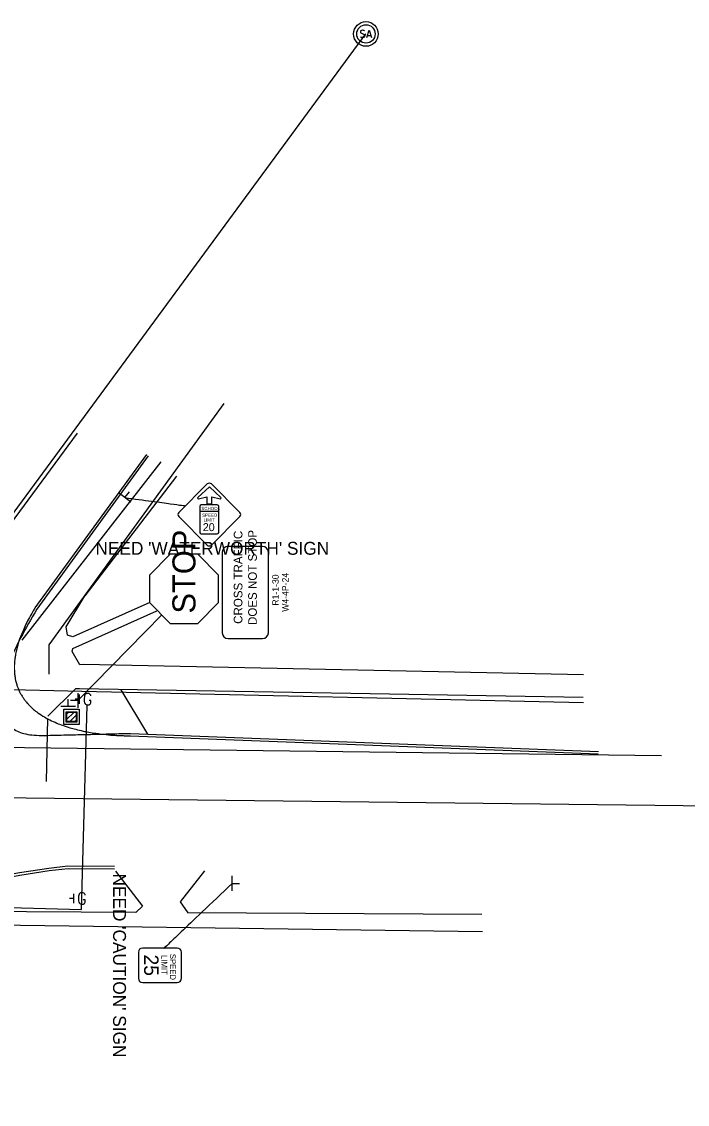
# Model space of a CAD drawing. Extents: x 108269 to 109415, y 548506 to 548874.
# Drawn here: x 109069.3 to 109213.8, y 548639.3 to 548874.1 of the extents above; entities that cross this region are included whole.
import ezdxf

# ---------------------------------------------------------------- set-up
doc = ezdxf.new("R2010")
doc.units = 0
for name, color, linetype in [('Default', 7, 'Continuous'), ('SC_Scratch1', 7, 'Continuous'), ('SH_Data', 7, 'Continuous'), ('SH_Text', 7, 'Continuous'), ('SN_P_Post', 7, 'Continuous'), ('SN_P_Signs', 7, 'Continuous'), ('SN_P_Text', 7, 'Continuous'), ('SN_X_Post', 7, 'Continuous'), ('SN_X_Public', 7, 'Continuous')]:
    doc.layers.add(name, color=color, linetype=linetype)

msp = doc.modelspace()

# ---------------------------------------------------------------- linework, layer by layer
at = {"layer": 'Default'}
for p, q in [((109144.06, 548873.47), (109144.06, 548873.47)), ((109022.45, 548706.36), (109144.06, 548871.47)), ((109144.06, 548871.47), (109144.06, 548871.47)), ((109144.06, 548871.47), (109144.06, 548871.47)), ((109144.06, 548871.47), (109144.06, 548871.47)), ((109144.06, 548869.47), (109144.06, 548869.47)), ((109048.43, 548740.21), (109081.46, 548784.86)), ((109096.41, 548780.23), (109072.22, 548746.98)), ((109096.81, 548779.93), (109072.63, 548746.68)), ((109099.53, 548778.68), (109069.36, 548739.94)), ((109102.97, 548775.55), (109083.03, 548749.59)), ((109078.99, 548742.87), (109083.03, 548749.59)), ((109080.41, 548738.19), (109098.7, 548746.34)), ((109097.19, 548748.16), (109080.47, 548740.7)), ((109079.25, 548741.06), (109078.99, 548742.87)), ((109080.47, 548740.7), (109079.25, 548741.06)), ((109080.3, 548737.51), (109080.41, 548738.19)), ((109081.95, 548734.64), (109080.3, 548737.51)), ((109082.76, 548734.69), (109081.95, 548734.64)), ((109191.28, 548732.44), (109082.76, 548734.69)), ((108915.58, 548732.79), (109082.36, 548728.91)), ((109081.01, 548729.39), (109074.99, 548723.51)), ((109081.88, 548729.38), (109081.01, 548729.39)), ((109191.25, 548727.49), (109081.88, 548729.38)), ((109081.91, 548726.16), (109081.91, 548728.16)), ((109082.36, 548728.91), (109191.28, 548726.42)), ((109090.84, 548729.22), (109096.63, 548719.59)), ((109080.16, 548724.97), (109080.16, 548724.97)), ((109081.91, 548727.16), (109080.95, 548727.16)), ((109082.29, 548681.55), (109083.58, 548725.84)), ((109074.92, 548722.94), (109074.65, 548709.3)), ((109079.01, 548722.69), (109080.77, 548724.45)), ((109079.01, 548723.82), (109079.64, 548724.45)), ((109079.16, 548723.31), (109079.16, 548723.31)), ((109079.61, 548722.16), (109081.3, 548723.85)), ((109080.16, 548724.31), (109080.16, 548724.31)), ((109080.16, 548723.31), (109080.16, 548723.31)), ((109080.16, 548723.31), (109080.16, 548723.31)), ((109080.16, 548723.31), (109080.16, 548723.31)), ((109080.74, 548722.16), (109081.3, 548722.72)), ((109081.16, 548723.31), (109081.16, 548723.31)), ((109080.16, 548722.31), (109080.16, 548722.31)), ((109080.16, 548721.64), (109080.16, 548721.64)), ((108918.1, 548718.65), (109208.22, 548714.91)), ((109092.91, 548719.24), (109194.49, 548715.29)), ((109092.93, 548719.74), (109194.51, 548715.79)), ((109022.45, 548706.36), (109415.28, 548701.66)), ((109038.39, 548682.7), (109082.29, 548681.55)), ((109080.65, 548683.92), (109079.7, 548683.92)), ((109080.65, 548682.92), (109080.65, 548684.92)), ((109169.23, 548680.47), (109105.39, 548680.84))]:
    msp.add_line(p, q, dxfattribs=at)
for points in [[(109143.73, 548872.16), (109143.71, 548872.19), (109143.67, 548872.21), (109143.56, 548872.25), (109143.42, 548872.27), (109143.32, 548872.27), (109143.28, 548872.27), (109143.11, 548872.24), (109142.98, 548872.16), (109142.89, 548872.06), (109142.86, 548871.96), (109142.86, 548871.88), (109142.89, 548871.78), (109142.99, 548871.69), (109143.68, 548871.32), (109143.74, 548871.27), (109143.77, 548871.22), (109143.79, 548871.14), (109143.79, 548871.06), (109143.78, 548870.99), (109143.77, 548870.94), (109143.74, 548870.88), (109143.72, 548870.83), (109143.69, 548870.79), (109143.66, 548870.75), (109143.62, 548870.72), (109143.57, 548870.7), (109143.53, 548870.69), (109143.42, 548870.67), (109143.24, 548870.67), (109143.13, 548870.7), (109142.96, 548870.79), (109142.86, 548870.86)], [(109144.27, 548870.67), (109144.78, 548872.27), (109145.27, 548870.67)], [(109145.14, 548871.05), (109144.4, 548871.05)], [(109075.31, 548732.62), (109075.31, 548738.96), (109113.31, 548791.33)], [(109084.38, 548727.92), (109084.36, 548728.01), (109084.3, 548728.11), (109084.2, 548728.21), (109084.07, 548728.33), (109083.97, 548728.37), (109083.89, 548728.39), (109083.77, 548728.41), (109083.54, 548728.41), (109083.44, 548728.39), (109083.38, 548728.37), (109083.3, 548728.33), (109083.14, 548728.21), (109083.04, 548728.07), (109082.98, 548727.92), (109082.94, 548727.7), (109082.91, 548727.38), (109082.91, 548726.97), (109082.93, 548726.64), (109083, 548726.38), (109083.12, 548726.14), (109083.22, 548726.07), (109083.34, 548725.99), (109083.56, 548725.91), (109083.77, 548725.91), (109083.99, 548725.95), (109084.07, 548725.99), (109084.15, 548726.03), (109084.22, 548726.1), (109084.3, 548726.22), (109084.38, 548726.4), (109084.38, 548726.89), (109083.97, 548726.89)], [(109040.44, 548687.78), (109037.09, 548682.73), (109039.51, 548682.67), (109056.29, 548686.61), (109068.96, 548688.99), (109075.29, 548689.96), (109079.4, 548690.41), (109089.48, 548690.37)], [(109089.48, 548690.87), (109079.37, 548690.91), (109075.22, 548690.46), (109068.87, 548689.49), (109056.19, 548687.1), (109039.46, 548683.17), (109038, 548683.21), (109040.86, 548687.51)], [(109089.67, 548689.85), (109095.56, 548682.28), (109094.15, 548680.9)], [(109109.02, 548689.95), (109103.73, 548683.19), (109105.39, 548680.84)], [(109094.15, 548680.9), (109034.73, 548681.25), (109040.71, 548688.79)], [(109083.13, 548684.68), (109083.11, 548684.78), (109083.05, 548684.88), (109082.95, 548684.98), (109082.81, 548685.09), (109082.71, 548685.13), (109082.63, 548685.15), (109082.52, 548685.17), (109082.28, 548685.17), (109082.18, 548685.15), (109082.12, 548685.13), (109082.04, 548685.09), (109081.89, 548684.98), (109081.79, 548684.84), (109081.73, 548684.68), (109081.69, 548684.46), (109081.65, 548684.15), (109081.65, 548683.74), (109081.67, 548683.4), (109081.75, 548683.14), (109081.87, 548682.91), (109081.96, 548682.83), (109082.08, 548682.75), (109082.3, 548682.67), (109082.52, 548682.67), (109082.73, 548682.71), (109082.81, 548682.75), (109082.89, 548682.79), (109082.97, 548682.87), (109083.05, 548682.99), (109083.13, 548683.16), (109083.13, 548683.66), (109082.71, 548683.66)], [(109169.39, 548676.69), (109032.13, 548678.6), (109004.75, 548639.27)]]:
    msp.add_lwpolyline(points, dxfattribs=at)
for points in [[(109078.49, 548724.97), (109081.82, 548724.97), (109081.82, 548721.64), (109078.49, 548721.64)], [(109079.01, 548724.45), (109081.3, 548724.45), (109081.3, 548722.16), (109079.01, 548722.16)], [(109079.16, 548724.31), (109081.16, 548724.31), (109081.16, 548722.31), (109079.16, 548722.31)]]:
    msp.add_lwpolyline(points, close=True, dxfattribs=at)
for radius in [2.67, 2, 2]:
    msp.add_circle((109144.06, 548871.47), radius, dxfattribs=at)
for points, degree in [([(109072.63, 548746.68), (109055.79, 548718.85), (109092.93, 548719.74), (109092.93, 548719.74)], 2), ([(109072.2, 548746.94), (109071.14, 548745.18), (109070.28, 548743.54), (109068.95, 548740.44), (109068.48, 548739), (109068.02, 548736.97), (109067.9, 548736.31), (109067.76, 548735.05), (109067.73, 548734.44), (109067.74, 548733.27), (109067.78, 548732.7), (109067.93, 548731.62), (109068.05, 548731.09), (109068.33, 548730.09), (109068.51, 548729.61), (109068.92, 548728.69), (109069.15, 548728.25), (109069.67, 548727.42), (109069.96, 548727.02), (109070.58, 548726.26), (109070.91, 548725.9), (109071.96, 548724.89), (109072.73, 548724.28), (109074.39, 548723.2), (109075.27, 548722.73), (109077.1, 548721.9), (109078.05, 548721.54), (109079.96, 548720.92), (109080.92, 548720.66), (109082.82, 548720.21), (109083.76, 548720.03), (109085.57, 548719.74), (109086.44, 548719.62), (109088.89, 548719.36), (109090.29, 548719.28), (109091.8, 548719.24), (109092.2, 548719.23), (109092.63, 548719.23), (109092.74, 548719.23), (109092.85, 548719.24), (109092.88, 548719.24), (109092.91, 548719.24), (109092.92, 548719.24), (109092.93, 548719.24), (109092.93, 548719.24), (109092.94, 548719.24), (109092.94, 548719.24), (109092.94, 548719.24)], 3)]:
    msp.add_open_spline(points, degree=degree, dxfattribs=at)
at = {"layer": 'SH_Data'}
for points in [[(109091.76, 548770.88), (109104.88, 548769.11), (109104.88, 548769.11), (109104.88, 548769.11)], [(109115.04, 548687.21), (109100.27, 548673.17), (109100.27, 548673.17), (109100.27, 548673.17)]]:
    msp.add_open_spline(points, degree=2, dxfattribs=at)
at = {"layer": 'SH_Text'}
msp.add_line((109081.52, 548726.86), (109099.73, 548745.43), dxfattribs=at)
at = {"layer": 'SN_P_Post'}
for p, q in [((109081.52, 548728.46), (109081.52, 548725.26)), ((109081.01, 548725.56), (109077.81, 548725.56)), ((109079.41, 548725.56), (109079.41, 548727.16)), ((109079.41, 548725.56), (109079.41, 548725.56)), ((109081.52, 548726.86), (109079.92, 548726.86)), ((109081.52, 548726.86), (109081.52, 548726.86))]:
    msp.add_line(p, q, dxfattribs=at)
at = {"layer": 'SN_P_Signs'}
for p, q in [((109101.56, 548758.6), (109097.06, 548754.1)), ((109107.56, 548758.6), (109101.56, 548758.6)), ((109112.06, 548754.1), (109107.56, 548758.6)), ((109097.06, 548754.1), (109097.06, 548748.1)), ((109112.06, 548748.1), (109112.06, 548754.1)), ((109097.06, 548748.1), (109101.56, 548743.6)), ((109107.56, 548743.6), (109112.06, 548748.1)), ((109101.56, 548743.6), (109107.56, 548743.6))]:
    msp.add_line(p, q, dxfattribs=at)
for points in [[(109121.63, 548760.29), (109114.13, 548760.29)], [(109112.88, 548759.04), (109112.88, 548741.54)], [(109122.88, 548741.54), (109122.88, 548759.04)], [(109114.13, 548740.29), (109121.63, 548740.29)]]:
    msp.add_lwpolyline(points, dxfattribs=at)
for centre, start, end in [((109114.13, 548759.04), 90, 180), ((109121.63, 548759.04), 0, 90), ((109114.13, 548741.54), 180, 270), ((109121.63, 548741.54), 270, 360)]:
    msp.add_arc(centre, 1.25, start, end, dxfattribs=at)
at = {"layer": 'SN_X_Post'}
for p, q in [((109091.76, 548770.88), (109092.74, 548772.14)), ((109093.02, 548769.9), (109090.5, 548771.86)), ((109091.76, 548770.88), (109091.76, 548770.88)), ((109115.04, 548685.61), (109115.04, 548688.81)), ((109115.04, 548687.21), (109116.64, 548687.21)), ((109115.04, 548687.21), (109115.04, 548687.21))]:
    msp.add_line(p, q, dxfattribs=at)
at = {"layer": 'SN_X_Public'}
for p, q in [((109110.07, 548773.26), (109107.58, 548770.91)), ((109112.56, 548770.91), (109110.07, 548773.26)), ((109107.73, 548770.62), (109109.51, 548771.04)), ((109109.51, 548771.04), (109109.51, 548769.51)), ((109110.62, 548769.51), (109110.62, 548771.04)), ((109110.62, 548771.04), (109112.4, 548770.62)), ((109112.15, 548767.86), (109107.98, 548767.86)), ((109109.51, 548769.51), (109110.62, 548769.51))]:
    msp.add_line(p, q, dxfattribs=at)
for points in [[(109109.62, 548773.85), (109103.44, 548767.66)], [(109116.7, 548767.66), (109110.51, 548773.85)], [(109107.98, 548768.95), (109107.98, 548763.4)], [(109111.8, 548769.3), (109108.33, 548769.3)], [(109112.15, 548763.4), (109112.15, 548768.95)], [(109103.44, 548766.78), (109109.62, 548760.59)], [(109110.51, 548760.59), (109116.7, 548766.78)], [(109108.33, 548763.05), (109111.8, 548763.05)], [(109094.67, 548672.24), (109094.67, 548666.61)], [(109103.1, 548673.17), (109095.6, 548673.17)], [(109104.04, 548666.61), (109104.04, 548672.24)], [(109095.6, 548665.67), (109103.1, 548665.67)]]:
    msp.add_lwpolyline(points, dxfattribs=at)
for centre, radius, start, end in [((109110.07, 548773.4), 0.625, 45, 135), ((109107.69, 548770.79), 0.17, 133.2643, 283.2405), ((109112.44, 548770.79), 0.17, 256.7595, 46.7357), ((109103.88, 548767.22), 0.625, 135, 225), ((109108.33, 548768.95), 0.347, 90, 180), ((109111.8, 548768.95), 0.347, 0, 90), ((109116.25, 548767.22), 0.625, 315, 45), ((109108.33, 548763.4), 0.347, 180, 270), ((109111.8, 548763.4), 0.347, 270, 0), ((109110.07, 548761.03), 0.625, 225, 315), ((109095.6, 548672.24), 0.938, 90, 180), ((109103.1, 548672.24), 0.938, 360, 90), ((109095.6, 548666.61), 0.938, 180, 270), ((109103.1, 548666.61), 0.938, 270, 360)]:
    msp.add_arc(centre, radius, start, end, dxfattribs=at)

# ---------------------------------------------------------------- texts
at = {"layer": 'SC_Scratch1'}
msp.add_text("NEED 'WATERWORTH' SIGN", height=2.8, dxfattribs=at).set_placement((109085.35, 548758.49))
msp.add_text("NEED 'CAUTION' SIGN", height=2.8, rotation=270, dxfattribs=at).set_placement((109089.18, 548689.35))
at = {"layer": 'SN_P_Signs'}
for s, height, p in [('STOP', 5, (109107.06, 548745.73)), ('CROSS TRAFFIC', 1.875, (109117.25, 548743.5)), ('DOES NOT STOP', 1.875, (109120.38, 548743.25))]:
    msp.add_text(s, height=height, rotation=90, dxfattribs=at).set_placement(p)
at = {"layer": 'SN_P_Text'}
for s, p in [('R1-1-30', (109125.13, 548747.46)), ('W4-4P-24', (109127.27, 548746.13))]:
    msp.add_text(s, height=1.4, rotation=90, dxfattribs=at).set_placement(p)
at = {"layer": 'SN_X_Public'}
for s, height, p in [('SCHOOL', 0.694, (109108.35, 548768.19)), ('SPEED', 0.694, (109108.51, 548766.73)), ('20', 1.736, (109108.65, 548763.61)), ('LIMIT', 0.694, (109108.83, 548765.69))]:
    msp.add_text(s, height=height, dxfattribs=at).set_placement(p)
for s, height, p in [('25', 3.125, (109095.92, 548671.77)), ('LIMIT', 1.25, (109099.67, 548671.65)), ('SPEED', 1.25, (109101.54, 548671.91))]:
    msp.add_text(s, height=height, rotation=270, dxfattribs=at).set_placement(p)

doc.saveas('drawing.dxf')
